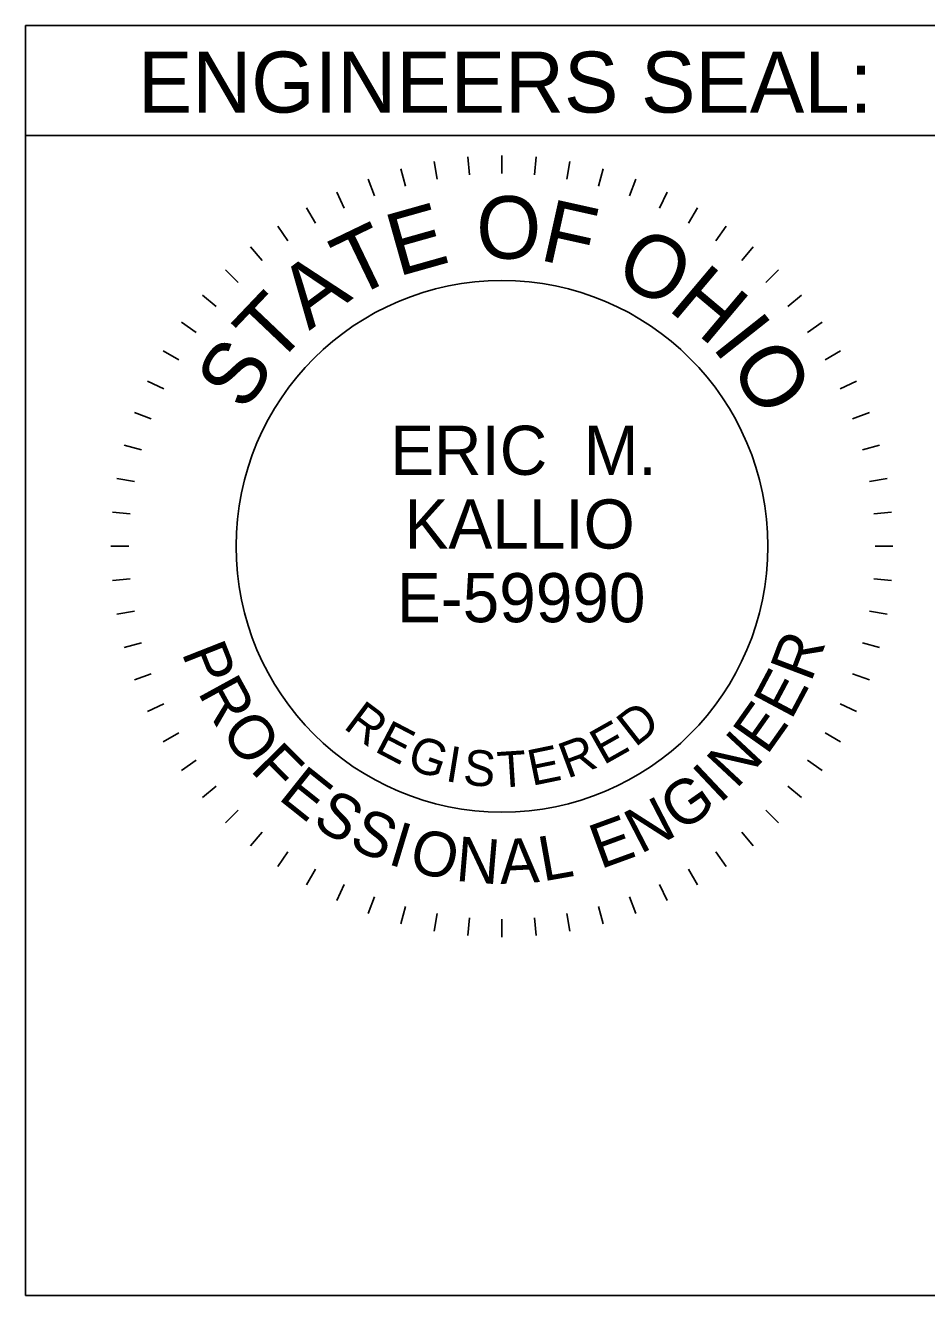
# Model space of a CAD drawing. Extents: x -17.5 to 72.9, y -57.8 to 32.3.
# Drawn here: x 46.64 to 50.67, y -57.83 to -52.14 of the extents above; entities that cross this region are included whole.
import ezdxf

# ---------------------------------------------------------------- set-up
doc = ezdxf.new("R2010")
doc.units = 0
doc.layers.add('SH_Data', color=7, linetype='Continuous')

msp = doc.modelspace()

# ---------------------------------------------------------------- linework, layer by layer
at = {"layer": 'SH_Data'}
for p, q in [((46.6362, -57.829), (46.6362, -52.1415)), ((46.6362, -52.1415), (50.8862, -52.1415)), ((46.6362, -52.6349), (50.8862, -52.6349)), ((48.4651, -52.7505), (48.479, -52.8293)), ((48.6164, -52.7306), (48.6234, -52.8103)), ((48.769, -52.7239), (48.769, -52.8039)), ((48.9215, -52.7306), (48.9145, -52.8103)), ((49.0728, -52.7505), (49.059, -52.8293)), ((48.1704, -52.8295), (48.1978, -52.9046)), ((48.316, -52.7836), (48.3367, -52.8608)), ((49.2219, -52.7836), (49.2012, -52.8608)), ((49.3675, -52.8295), (49.3401, -52.9046)), ((48.0294, -52.8879), (48.0632, -52.9604)), ((49.5085, -52.8879), (49.4747, -52.9604)), ((47.894, -52.9584), (47.934, -53.0277)), ((49.644, -52.9584), (49.604, -53.0277)), ((47.7652, -53.0404), (47.8111, -53.106)), ((49.7727, -53.0404), (49.7268, -53.106)), ((47.6441, -53.1334), (47.6955, -53.1946)), ((49.8938, -53.1334), (49.8424, -53.1946)), ((47.5315, -53.2365), (47.5881, -53.2931)), ((50.0064, -53.2365), (49.9498, -53.2931)), ((47.4284, -53.3491), (47.4897, -53.4005)), ((50.1095, -53.3491), (50.0483, -53.4005)), ((47.3354, -53.4702), (47.401, -53.5161)), ((50.2025, -53.4702), (50.1369, -53.5161)), ((47.2534, -53.5989), (47.3227, -53.6389)), ((50.2845, -53.5989), (50.2152, -53.6389)), ((47.1829, -53.7344), (47.2554, -53.7682)), ((50.355, -53.7344), (50.2825, -53.7682)), ((47.1245, -53.8754), (47.1997, -53.9028)), ((50.4134, -53.8754), (50.3383, -53.9028)), ((47.0786, -54.021), (47.1559, -54.0417)), ((50.4593, -54.021), (50.3821, -54.0417)), ((47.0456, -54.1701), (47.1243, -54.1839)), ((50.4924, -54.1701), (50.4136, -54.1839)), ((47.0256, -54.3214), (47.1053, -54.3284)), ((50.5123, -54.3214), (50.4326, -54.3284)), ((47.019, -54.4739), (47.099, -54.4739)), ((50.519, -54.4739), (50.439, -54.4739)), ((47.0256, -54.6265), (47.1053, -54.6195)), ((50.5123, -54.6265), (50.4326, -54.6195)), ((47.0456, -54.7778), (47.1243, -54.7639)), ((50.4924, -54.7778), (50.4136, -54.7639)), ((47.0786, -54.9269), (47.1559, -54.9062)), ((50.4593, -54.9269), (50.3821, -54.9062)), ((47.1245, -55.0725), (47.1997, -55.0451)), ((50.4134, -55.0725), (50.3383, -55.0451)), ((47.1829, -55.2135), (47.2554, -55.1797)), ((50.355, -55.2135), (50.2825, -55.1797)), ((47.2534, -55.3489), (47.3227, -55.3089)), ((50.2845, -55.3489), (50.2152, -55.3089)), ((47.3354, -55.4777), (47.401, -55.4318)), ((50.2025, -55.4777), (50.1369, -55.4318)), ((47.4284, -55.5988), (47.4897, -55.5474)), ((50.1095, -55.5988), (50.0483, -55.5474)), ((47.5315, -55.7114), (47.5881, -55.6548)), ((50.0064, -55.7114), (49.9498, -55.6548)), ((47.6441, -55.8145), (47.6955, -55.7532)), ((49.8938, -55.8145), (49.8424, -55.7532)), ((47.7652, -55.9075), (47.8111, -55.8419)), ((49.7727, -55.9075), (49.7268, -55.8419)), ((47.894, -55.9895), (47.934, -55.9202)), ((49.644, -55.9895), (49.604, -55.9202)), ((48.0294, -56.06), (48.0632, -55.9875)), ((49.5085, -56.06), (49.4747, -55.9875)), ((48.1704, -56.1184), (48.1978, -56.0432)), ((49.3675, -56.1184), (49.3401, -56.0432)), ((48.316, -56.1643), (48.3367, -56.087)), ((48.4651, -56.1973), (48.479, -56.1186)), ((49.0728, -56.1973), (49.059, -56.1186)), ((49.2219, -56.1643), (49.2012, -56.087)), ((48.6164, -56.2173), (48.6234, -56.1376)), ((48.769, -56.2239), (48.769, -56.1439)), ((48.9215, -56.2173), (48.9145, -56.1376)), ((46.6362, -57.829), (50.8862, -57.829))]:
    msp.add_line(p, q, dxfattribs=at)
msp.add_circle((48.769, -54.4739), 1.19, dxfattribs=at)

# ---------------------------------------------------------------- texts
for s, height, p in [('ENGINEERS SEAL:', 0.273, (47.1397, -52.5319)), ('ERIC  M.', 0.22, (48.2686, -54.1539)), ('KALLIO', 0.22, (48.333, -54.4839)), ('E-59990', 0.22, (48.2988, -54.8139))]:
    msp.add_text(s, height=height, dxfattribs=at).set_placement(p)
for s, height, rotation, p in [('E', 0.28, 15.7571, (48.3028, -53.2672)), ('O', 0.28, 359.7812, (48.653, -53.1855)), ('F', 0.28, 347.4362, (48.9311, -53.1905)), ('T', 0.28, 25.7167, (48.1011, -53.366)), ('O', 0.28, 332.2586, (49.2615, -53.2777)), ('A', 0.28, 36.4747, (47.9061, -53.5101)), ('H', 0.28, 319.9136, (49.5058, -53.4107)), ('T', 0.28, 46.4344, (47.7524, -53.6739)), ('I', 0.28, 308.367, (49.7038, -53.5797)), ('S', 0.28, 57.1924, (47.6209, -53.8777)), ('O', 0.28, 303.1491, (49.7812, -53.6684)), ('R', 0.2, 69.2322, (50.1515, -55.0867)), ('P', 0.2, 291.494, (47.3337, -54.9502)), ('R', 0.2, 298.7311, (47.4051, -55.1272)), ('E', 0.2, 61.9951, (50.0633, -55.256)), ('R', 0.16, 323.2378, (48.0545, -55.2858)), ('E', 0.2, 54.758, (49.9545, -55.4128)), ('D', 0.16, 38.0378, (49.3651, -55.3762)), ('O', 0.2, 306.4666, (47.5054, -55.3049)), ('E', 0.16, 332.4256, (48.1933, -55.3895)), ('E', 0.16, 29.4558, (49.2238, -55.4551)), ('G', 0.16, 341.0076, (48.3364, -55.4651)), ('R', 0.16, 20.268, (49.0613, -55.5151)), ('N', 0.2, 47.0224, (49.8173, -55.5639)), ('F', 0.2, 314.7068, (47.6376, -55.4774)), ('I', 0.16, 350.8085, (48.5114, -55.5243)), ('S', 0.16, 355.1352, (48.5914, -55.5407)), ('T', 0.16, 3.7172, (48.7526, -55.5553)), ('E', 0.16, 11.686, (48.9027, -55.5471)), ('I', 0.2, 43.287, (49.7441, -55.6298)), ('E', 0.2, 321.4393, (47.763, -55.6031)), ('G', 0.2, 35.0469, (49.5683, -55.7577)), ('S', 0.2, 328.6764, (47.9133, -55.7208)), ('N', 0.2, 27.3113, (49.3883, -55.8536)), ('S', 0.2, 335.9134, (48.0772, -55.8187)), ('E', 0.2, 20.0742, (49.2095, -55.9206)), ('I', 0.2, 343.1505, (48.2521, -55.8951)), ('O', 0.2, 346.8859, (48.3458, -55.9258)), ('N', 0.2, 355.1261, (48.5582, -55.9714)), ('A', 0.2, 2.8617, (48.7617, -55.9862)), ('L', 0.2, 10.0987, (48.9523, -55.975))]:
    msp.add_text(s, height=height, rotation=rotation, dxfattribs=at).set_placement(p)

doc.saveas('drawing.dxf')
